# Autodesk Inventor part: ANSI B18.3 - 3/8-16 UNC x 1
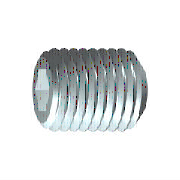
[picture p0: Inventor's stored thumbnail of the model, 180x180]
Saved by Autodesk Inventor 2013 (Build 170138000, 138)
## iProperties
Created: 2010-02
Part Number: ANSI B18.3 - 3/8-16 UNC x 1
Material: Steel, Mild
Description: Hexagon Socket Set Screw - Flat Point
Document SubType Name: Modeling
Standard: ANSI B18.3
Designer: akp3
Standard Revision: 2003
Standards Organization: ANSI
Language: en-US
Size Designation: 3/8-16 UNC x 1
Categories: <MemberInstance><Categories><Category DisplayName="Fasteners" InternalName="e4da775c-781d-43d5-af7c-5136215cf5a6" Mnemonic="FSTN"><Category DisplayName="Bolts"
Density: 1 g/cm^3
IsCustomPart: 0
Author: akp3
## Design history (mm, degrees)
sketch "Sketch1"
  geometry: L1 (0, 0)-(19.033, 0); L2 (25.4, 2.757)-(25.4, 4.763); L3 (25.4, 4.763)-(0, 4.762); L4 (25.4, 2.757)-(20.625, 2.757); L5 (20.625, 2.757)-(19.033, 0); L6 (0, -0.953)-(0, 5.715) reference; L7 (0, 4.762)-(0, 0)
  constraints: 13 end point, 3 parallel, 1 collinear, 1 perpendicular, 1 point on line
  dimensions: "d0" = 4.7752 distance of L2.start L4.end (= INTI); "d1" = 60 deg angle of L5 L1; "d2" = 9.525 diameter of L3 L1 (= NND); "d3" = 5.51393 diameter of L4 L1 (= 1.1547 x SW); "d5" = 25.4 distance from line of L2 L3.end (= NLG)
revolve "Body" sketch "Sketch1" stored, may be unused: angle "d6" = 90 deg
sketch "Sketch2"
  geometry: L1 (-1.378, 2.388)-(1.378, 2.388); L2 (1.378, 2.388)-(2.757, 0); L3 (2.757, 0)-(1.378, -2.388); L4 (1.378, -2.388)-(-1.378, -2.388); L5 (-1.378, -2.388)-(-2.757, 0); L6 (-2.757, 0)-(-1.378, 2.388); A1 r 2.757 centre (0, 0) between (-1.378, 2.388) and (1.378, 2.388) reference; 2 further points
  constraints: 12 end point, 2 point on circle, 1 coincident, 1 horizontal, 11 other
extrude "Slot" join sketch "Sketch2" taper "d9" = 0 deg; stored distance "d21" = 10
workaxis "Work Axis1"
workplane "Work Plane1"
body "Solid1"
chamfer "Chamfer1" distance "d7" = 0.97383 (= -0.5 x GD1 + 0.5 x NND); stored, may be unused: angle "d8" = 45 deg (= FAWI), second distance "d29" = 0.97383 (= -0.5 x GD1 + 0.5 x NND)
feature "Thread" dims "d11" = 25.4 (= NLG), "d12" = 0
chamfer "Chamfer2" distance "d13" = 0.97383 (= -0.5 x GD1 + 0.5 x NND); stored, may be unused: angle "d14" = 45 deg (= FAWI), second distance "d30" = 0.97383 (= -0.5 x GD1 + 0.5 x NND)
other parameters: "NND" = 9.525 [user parameter; used in 5 equation terms], "NLG" = 25.4 [user parameter; used in 2 equation terms], "INTI" = 4.7752 [user parameter; used in 1 equation term], "FAWI" = 45 deg [user parameter; used in 2 equation terms], "SW" = 4.7752 [user parameter; used in 2 equation terms], "GD1" = 7.57734 [user parameter; used in 4 equation terms], "d4" = 0, "FAWI1" = 7.85398 [user parameter], "d15" = 0, "d31" = 0, "SPD" = 5.3848 [user parameter], "SEWI" = 90 deg [user parameter], "TOA" = 30 deg [user parameter], "ZLG" = 2.5146 [user parameter], "ZD" = 6.35 [user parameter], "HHPTC" = 1.5875 [user parameter], "PTC" = 1.5875 (computed from TPU) [user parameter], "THREADDIA" = 9.525 [user parameter], "OPR" = 7.1374 [user parameter], "E0" = 5.51536 (= 1.155 x SW) [user parameter]
